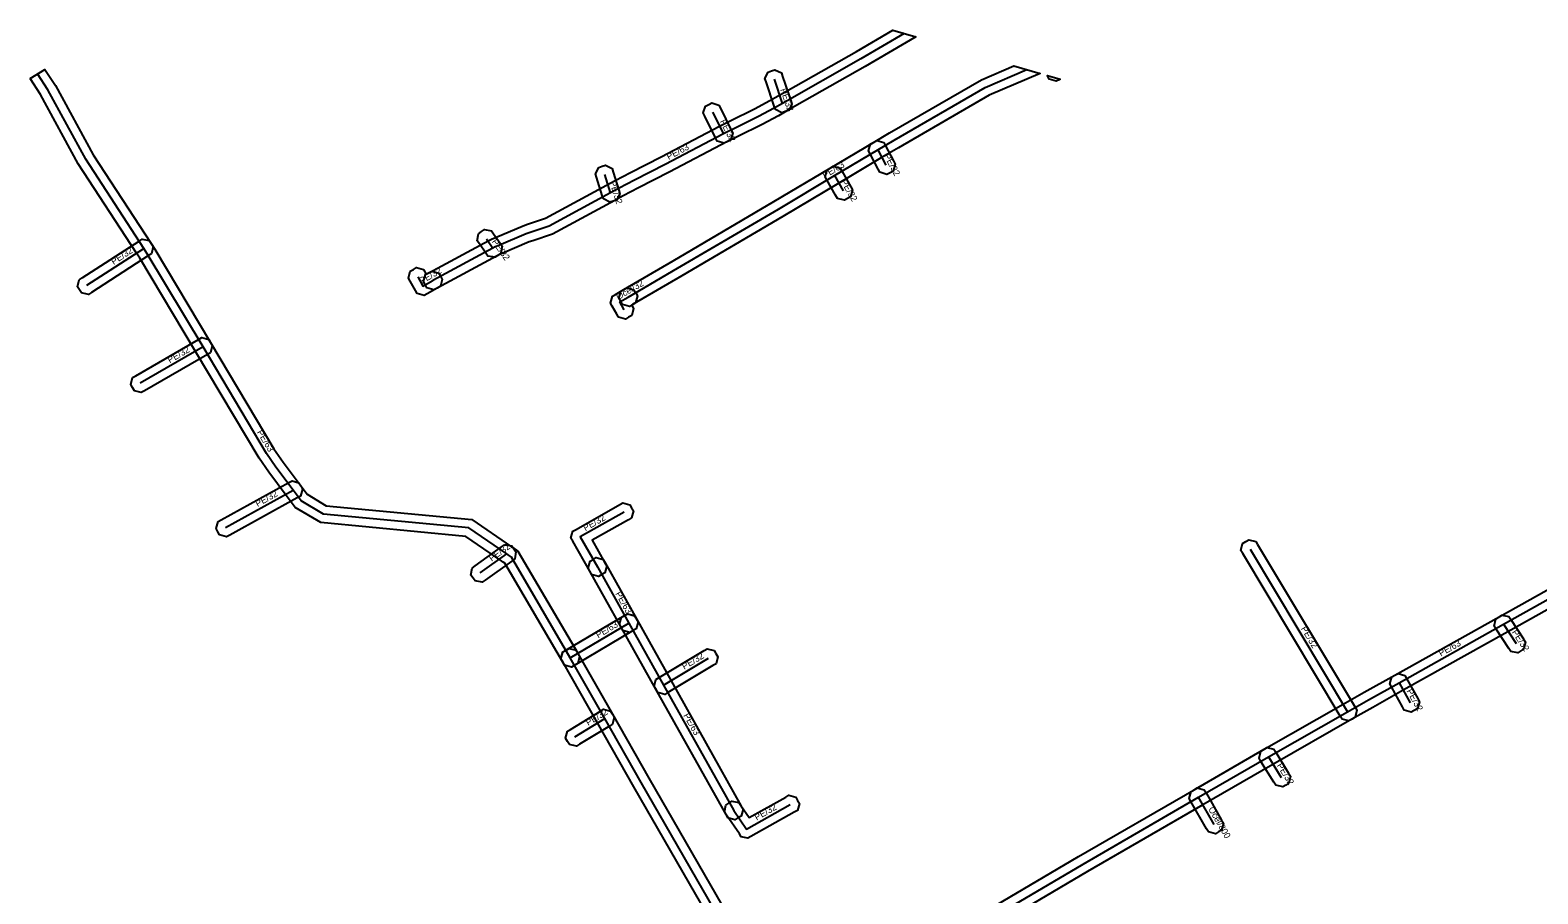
# Model space of a CAD drawing. Extents: x -574390 to -573768, y -1190959 to -1190603.
# Drawn here: x -574153.3 to -573979.8, y -1190702.4 to -1190603.1 of the extents above; entities that cross this region are included whole.
import ezdxf

# ---------------------------------------------------------------- set-up
doc = ezdxf.new("R2010")
doc.units = 0
for name, color, linetype in [('1', 7, 'Continuous'), ('24', 7, 'Continuous'), ('28', 7, 'Continuous'), ('30', 7, 'Continuous')]:
    doc.layers.add(name, color=color, linetype=linetype)

msp = doc.modelspace()

# ---------------------------------------------------------------- linework, layer by layer
at = {"layer": '1'}
for points in [[(-574058.179, -1190605.494), (-574054.01, -1190603.056), (-574051.371, -1190603.829), (-574057.181, -1190607.226), (-574066.205, -1190612.349), (-574067.176, -1190612.905), (-574069.024, -1190613.89), (-574071.846, -1190615.282), (-574072.739, -1190615.723), (-574073.038, -1190615.877), (-574079.739, -1190619.397), (-574083.264, -1190621.207), (-574085.032, -1190622.114), (-574086.012, -1190622.648), (-574093.161, -1190626.531), (-574095.428, -1190627.28), (-574095.85, -1190627.418), (-574098.964, -1190628.733), (-574099.33, -1190628.884), (-574099.545, -1190629), (-574106.455, -1190632.73), (-574106.82, -1190632.927), (-574107.613, -1190632.69), (-574107.81, -1190632.325), (-574108.007, -1190631.96), (-574107.77, -1190631.167), (-574107.405, -1190630.97), (-574100.495, -1190627.24), (-574100.19, -1190627.076), (-574099.736, -1190626.887), (-574096.55, -1190625.542), (-574096.052, -1190625.38), (-574093.959, -1190624.689), (-574086.968, -1190620.892), (-574085.968, -1190620.346), (-574084.178, -1190619.427), (-574080.661, -1190617.623), (-574073.962, -1190614.103), (-574073.641, -1190613.937), (-574072.73, -1190613.488), (-574069.936, -1190612.11), (-574068.144, -1190611.155), (-574067.195, -1190610.611)], [(-574153.281, -1190608.611), (-574151.577, -1190607.562), (-574150.371, -1190609.417), (-574146.021, -1190617.387), (-574139.361, -1190627.606), (-574138.95, -1190628.242), (-574132.532, -1190638.977), (-574125.228, -1190651.2), (-574124.177, -1190652.728), (-574122.218, -1190655.362), (-574121.419, -1190656.431), (-574119.202, -1190657.746), (-574102.458, -1190659.339), (-574097.88, -1190662.471), (-574097.728, -1190662.573), (-574097.149, -1190662.974), (-574090.257, -1190674.724), (-574090.048, -1190675.081), (-574090.257, -1190675.883), (-574090.614, -1190676.093), (-574090.971, -1190676.302), (-574091.773, -1190676.093), (-574091.983, -1190675.736), (-574098.651, -1190664.366), (-574098.852, -1190664.227), (-574099, -1190664.129), (-574103.162, -1190661.281), (-574119.838, -1190659.694), (-574122.781, -1190657.949), (-574123.822, -1190656.558), (-574125.803, -1190653.892), (-574126.912, -1190652.28), (-574134.248, -1190640.003), (-574140.65, -1190629.298), (-574141.039, -1190628.694), (-574147.739, -1190618.413), (-574152.089, -1190610.443)], [(-574043.82, -1190608.755), (-574040.073, -1190607.14), (-574037.065, -1190608.021), (-574042.92, -1190610.545), (-574053.365, -1190616.583), (-574055.22, -1190617.68), (-574060.209, -1190620.649), (-574066.672, -1190624.491), (-574078.284, -1190631.303), (-574083.955, -1190634.623), (-574084.312, -1190634.832), (-574085.114, -1190634.622), (-574085.323, -1190634.265), (-574085.532, -1190633.908), (-574085.322, -1190633.106), (-574084.965, -1190632.897), (-574079.296, -1190629.577), (-574067.688, -1190622.769), (-574061.231, -1190618.931), (-574056.24, -1190615.96), (-574054.375, -1190614.857)], [(-574067.515, -1190612.192), (-574067.648, -1190611.799), (-574068.588, -1190609.009), (-574068.72, -1190608.617), (-574068.352, -1190607.875), (-574067.959, -1190607.742), (-574067.567, -1190607.61), (-574066.825, -1190607.978), (-574066.692, -1190608.371), (-574065.752, -1190611.161), (-574065.62, -1190611.553), (-574065.988, -1190612.295), (-574066.381, -1190612.428), (-574066.773, -1190612.56)], [(-574036.192, -1190608.312), (-574036.213, -1190608.271), (-574034.746, -1190608.7), (-574034.848, -1190608.752), (-574035.217, -1190608.939), (-574036.005, -1190608.681)], [(-574074.041, -1190611.672), (-574073.856, -1190612.043), (-574072.606, -1190614.543), (-574072.42, -1190614.913), (-574072.682, -1190615.699), (-574073.053, -1190615.884), (-574073.423, -1190616.07), (-574074.209, -1190615.808), (-574074.394, -1190615.437), (-574075.644, -1190612.937), (-574075.83, -1190612.567), (-574075.568, -1190611.781), (-574075.197, -1190611.596), (-574074.827, -1190611.41)], [(-574055.041, -1190615.985), (-574054.847, -1190616.351), (-574053.917, -1190618.101), (-574053.723, -1190618.467), (-574053.965, -1190619.259), (-574054.331, -1190619.453), (-574054.697, -1190619.647), (-574055.489, -1190619.405), (-574055.683, -1190619.039), (-574056.613, -1190617.289), (-574056.807, -1190616.923), (-574056.565, -1190616.131), (-574056.199, -1190615.937), (-574055.833, -1190615.743)], [(-574087.32, -1190622.465), (-574087.444, -1190622.07), (-574088.104, -1190619.97), (-574088.228, -1190619.575), (-574087.845, -1190618.84), (-574087.45, -1190618.716), (-574087.055, -1190618.592), (-574086.32, -1190618.975), (-574086.196, -1190619.37), (-574085.536, -1190621.47), (-574085.412, -1190621.865), (-574085.795, -1190622.6), (-574086.19, -1190622.724), (-574086.585, -1190622.848)], [(-574060.056, -1190618.936), (-574059.851, -1190619.296), (-574058.851, -1190621.056), (-574058.646, -1190621.416), (-574058.866, -1190622.214), (-574059.226, -1190622.419), (-574059.586, -1190622.624), (-574060.384, -1190622.404), (-574060.589, -1190622.044), (-574061.589, -1190620.284), (-574061.794, -1190619.924), (-574061.574, -1190619.126), (-574061.214, -1190618.921), (-574060.854, -1190618.716)], [(-574100.189, -1190626.137), (-574099.951, -1190626.476), (-574099.201, -1190627.546), (-574098.963, -1190627.885), (-574099.107, -1190628.701), (-574099.446, -1190628.939), (-574099.785, -1190629.177), (-574100.601, -1190629.033), (-574100.839, -1190628.694), (-574101.589, -1190627.624), (-574101.827, -1190627.285), (-574101.683, -1190626.469), (-574101.344, -1190626.231), (-574101.005, -1190625.993)], [(-574147.651, -1190631.775), (-574147.303, -1190631.55), (-574140.743, -1190627.31), (-574140.395, -1190627.085), (-574139.585, -1190627.259), (-574139.36, -1190627.607), (-574139.135, -1190627.955), (-574139.309, -1190628.765), (-574139.657, -1190628.99), (-574146.217, -1190633.23), (-574146.565, -1190633.455), (-574147.375, -1190633.281), (-574147.6, -1190632.933), (-574147.825, -1190632.585)], [(-574108.014, -1190630.587), (-574107.81, -1190630.947), (-574107.702, -1190631.138), (-574107.422, -1190630.979), (-574107.061, -1190630.775), (-574106.263, -1190630.997), (-574106.059, -1190631.358), (-574105.855, -1190631.719), (-574106.077, -1190632.517), (-574106.438, -1190632.721), (-574107.588, -1190633.371), (-574107.948, -1190633.574), (-574108.746, -1190633.353), (-574108.95, -1190632.993), (-574109.55, -1190631.933), (-574109.754, -1190631.572), (-574109.533, -1190630.774), (-574109.173, -1190630.57), (-574108.812, -1190630.366)], [(-574085.576, -1190636.063), (-574085.78, -1190635.703), (-574086.29, -1190634.803), (-574086.494, -1190634.444), (-574086.275, -1190633.647), (-574085.917, -1190633.442), (-574084.957, -1190632.892), (-574084.597, -1190632.686), (-574083.798, -1190632.903), (-574083.592, -1190633.263), (-574083.386, -1190633.623), (-574083.603, -1190634.422), (-574083.963, -1190634.628), (-574084.059, -1190634.683), (-574084.04, -1190634.717), (-574083.836, -1190635.077), (-574084.057, -1190635.876), (-574084.417, -1190636.08), (-574084.777, -1190636.284)], [(-574132.531, -1190640.149), (-574132.89, -1190640.356), (-574140.13, -1190644.536), (-574140.489, -1190644.743), (-574141.289, -1190644.529), (-574141.496, -1190644.17), (-574141.703, -1190643.811), (-574141.489, -1190643.011), (-574141.13, -1190642.804), (-574133.89, -1190638.624), (-574133.531, -1190638.417), (-574132.731, -1190638.631), (-574132.524, -1190638.99), (-574132.317, -1190639.349)], [(-574131.646, -1190659.585), (-574131.284, -1190659.385), (-574123.504, -1190655.085), (-574123.142, -1190654.885), (-574122.345, -1190655.114), (-574122.145, -1190655.476), (-574121.945, -1190655.838), (-574122.174, -1190656.635), (-574122.536, -1190656.835), (-574130.316, -1190661.135), (-574130.678, -1190661.335), (-574131.475, -1190661.106), (-574131.675, -1190660.744), (-574131.875, -1190660.382)], [(-574084.077, -1190659.156), (-574084.438, -1190659.36), (-574088.605, -1190661.717), (-574087.131, -1190664.305), (-574086.926, -1190664.665), (-574087.145, -1190665.464), (-574087.505, -1190665.669), (-574087.865, -1190665.874), (-574088.664, -1190665.655), (-574088.869, -1190665.295), (-574090.839, -1190661.835), (-574091.044, -1190661.474), (-574090.934, -1190661.074), (-574090.824, -1190660.674), (-574090.462, -1190660.47), (-574085.422, -1190657.62), (-574085.062, -1190657.416), (-574084.264, -1190657.637), (-574084.06, -1190657.998), (-574083.856, -1190658.358)], [(-574102.419, -1190664.918), (-574102.082, -1190664.677), (-574099.022, -1190662.487), (-574098.685, -1190662.246), (-574097.868, -1190662.381), (-574097.627, -1190662.718), (-574097.386, -1190663.055), (-574097.521, -1190663.872), (-574097.858, -1190664.113), (-574100.918, -1190666.303), (-574101.255, -1190666.544), (-574102.072, -1190666.409), (-574102.313, -1190666.072), (-574102.554, -1190665.735)], [(-574012.235, -1190661.861), (-574012.022, -1190662.216), (-574000.812, -1190680.926), (-574000.599, -1190681.281), (-574000.801, -1190682.085), (-574001.156, -1190682.298), (-574001.511, -1190682.511), (-574002.315, -1190682.309), (-574002.528, -1190681.954), (-574013.738, -1190663.244), (-574013.951, -1190662.889), (-574013.749, -1190662.085), (-574013.394, -1190661.872), (-574013.039, -1190661.659)], [(-574087.33, -1190663.95), (-574087.127, -1190664.312), (-574083.517, -1190670.762), (-574083.315, -1190671.123), (-574083.54, -1190671.92), (-574083.902, -1190672.123), (-574084.263, -1190672.325), (-574085.06, -1190672.1), (-574085.263, -1190671.738), (-574088.873, -1190665.288), (-574089.075, -1190664.927), (-574088.85, -1190664.13), (-574088.488, -1190663.927), (-574088.127, -1190663.725)], [(-574091.986, -1190674.58), (-574091.629, -1190674.369), (-574084.899, -1190670.389), (-574084.542, -1190670.178), (-574083.74, -1190670.384), (-574083.529, -1190670.741), (-574083.318, -1190671.098), (-574083.524, -1190671.9), (-574083.881, -1190672.111), (-574090.611, -1190676.091), (-574090.968, -1190676.302), (-574091.77, -1190676.096), (-574091.981, -1190675.739), (-574092.192, -1190675.382)], [(-574083.72, -1190670.4), (-574083.517, -1190670.762), (-574079.528, -1190677.891), (-574071.448, -1190692.301), (-574071.245, -1190692.662), (-574071.47, -1190693.459), (-574071.831, -1190693.662), (-574072.192, -1190693.865), (-574072.989, -1190693.64), (-574073.192, -1190693.279), (-574081.272, -1190678.869), (-574085.263, -1190671.738), (-574085.465, -1190671.377), (-574085.24, -1190670.58), (-574084.878, -1190670.377), (-574084.517, -1190670.175)], [(-573983.12, -1190670.496), (-573982.893, -1190670.843), (-573981.443, -1190673.063), (-573981.216, -1190673.41), (-573981.386, -1190674.22), (-573981.733, -1190674.447), (-573982.08, -1190674.674), (-573982.89, -1190674.504), (-573983.117, -1190674.157), (-573984.567, -1190671.937), (-573984.794, -1190671.59), (-573984.624, -1190670.78), (-573984.277, -1190670.553), (-573983.93, -1190670.326)], [(-574081.269, -1190677.734), (-574080.914, -1190677.522), (-574075.734, -1190674.422), (-574075.378, -1190674.209), (-574074.574, -1190674.411), (-574074.362, -1190674.766), (-574074.149, -1190675.122), (-574074.351, -1190675.926), (-574074.706, -1190676.138), (-574079.886, -1190679.238), (-574080.242, -1190679.451), (-574081.046, -1190679.249), (-574081.258, -1190678.894), (-574081.471, -1190678.538)], [(-573995.073, -1190677.265), (-573994.874, -1190677.628), (-573993.604, -1190679.938), (-573993.404, -1190680.301), (-573993.635, -1190681.097), (-573993.998, -1190681.296), (-573994.361, -1190681.496), (-573995.157, -1190681.265), (-573995.356, -1190680.902), (-573996.626, -1190678.592), (-573996.826, -1190678.229), (-573996.595, -1190677.433), (-573996.232, -1190677.234), (-573995.869, -1190677.034)], [(-574091.463, -1190683.7), (-574091.109, -1190683.485), (-574087.649, -1190681.385), (-574087.295, -1190681.17), (-574086.49, -1190681.367), (-574086.275, -1190681.721), (-574086.06, -1190682.075), (-574086.257, -1190682.88), (-574086.611, -1190683.095), (-574090.071, -1190685.195), (-574090.425, -1190685.41), (-574091.23, -1190685.213), (-574091.445, -1190684.859), (-574091.66, -1190684.505)], [(-574010.156, -1190685.753), (-574009.939, -1190686.105), (-574008.459, -1190688.505), (-574008.242, -1190688.857), (-574008.433, -1190689.664), (-574008.785, -1190689.881), (-574009.137, -1190690.098), (-574009.944, -1190689.907), (-574010.161, -1190689.555), (-574011.641, -1190687.155), (-574011.858, -1190686.803), (-574011.667, -1190685.996), (-574011.315, -1190685.779), (-574010.963, -1190685.562)], [(-574017.689, -1190695.259), (-574017.896, -1190694.9), (-574019.696, -1190691.78), (-574019.903, -1190691.421), (-574019.689, -1190690.621), (-574019.33, -1190690.414), (-574018.971, -1190690.207), (-574018.171, -1190690.421), (-574017.964, -1190690.78), (-574016.164, -1190693.9), (-574015.957, -1190694.259), (-574016.171, -1190695.059), (-574016.53, -1190695.266), (-574016.889, -1190695.473)], [(-574071.731, -1190691.882), (-574071.496, -1190692.223), (-574070.534, -1190693.622), (-574066.319, -1190691.258), (-574065.958, -1190691.055), (-574065.161, -1190691.28), (-574064.958, -1190691.641), (-574064.755, -1190692.002), (-574064.98, -1190692.799), (-574065.341, -1190693.002), (-574070.351, -1190695.812), (-574070.689, -1190696.001), (-574071.444, -1190695.826), (-574071.664, -1190695.507), (-574073.144, -1190693.357), (-574073.379, -1190693.016), (-574073.228, -1190692.201), (-574072.887, -1190691.966), (-574072.546, -1190691.731)]]:
    msp.add_lwpolyline(points, close=True, dxfattribs=at)
for points in [[(-574044.527, -1190705.118), (-574032.624, -1190698.106), (-574019.331, -1190690.414), (-574011.288, -1190685.763), (-574002.164, -1190680.57), (-573999.761, -1190679.209), (-573996.238, -1190677.237), (-573984.218, -1190670.517), (-573976.478, -1190666.187)], [(-573975.502, -1190667.933), (-573983.242, -1190672.263), (-573995.262, -1190678.983), (-573998.779, -1190680.951), (-574001.176, -1190682.31), (-574010.292, -1190687.497), (-574018.329, -1190692.146), (-574031.616, -1190699.834), (-574043.513, -1190706.842)], [(-574074.657, -1190706.008), (-574083.818, -1190690.077), (-574087.999, -1190682.735), (-574091.989, -1190675.725), (-574092.194, -1190675.365), (-574091.975, -1190674.566), (-574091.615, -1190674.361), (-574091.255, -1190674.156), (-574090.456, -1190674.375), (-574090.251, -1190674.735), (-574086.261, -1190681.745), (-574082.082, -1190689.083), (-574072.923, -1190705.012)]]:
    msp.add_lwpolyline(points, dxfattribs=at)
at = {"layer": '24'}
for points in [[(-574052.690742, -1190603.442677), (-574057.68, -1190606.36), (-574066.7, -1190611.48), (-574067.66, -1190612.03), (-574069.48, -1190613), (-574072.288, -1190614.385), (-574073.19, -1190614.83), (-574073.5, -1190614.99), (-574080.2, -1190618.51), (-574083.721, -1190620.317), (-574085.5, -1190621.23), (-574086.49, -1190621.77), (-574093.56, -1190625.61), (-574095.74, -1190626.33), (-574096.2, -1190626.48), (-574099.35, -1190627.81), (-574099.76, -1190627.98), (-574100.02, -1190628.12), (-574106.93, -1190631.85)], [(-574091.12, -1190675.23), (-574097.9, -1190663.67), (-574098.29, -1190663.4), (-574098.44, -1190663.3), (-574102.81, -1190660.31), (-574119.52, -1190658.72), (-574122.1, -1190657.19), (-574123.02, -1190655.96), (-574124.99, -1190653.31), (-574126.07, -1190651.74), (-574133.39, -1190639.49), (-574139.8, -1190628.77), (-574140.2, -1190628.15), (-574146.88, -1190617.9), (-574151.23, -1190609.93), (-574152.428958, -1190608.086651)], [(-574084.46, -1190633.76), (-574078.79, -1190630.44), (-574067.18, -1190623.63), (-574060.72, -1190619.79), (-574055.73, -1190616.82), (-574053.87, -1190615.72), (-574043.37, -1190609.65), (-574038.568701, -1190607.580343)], [(-574074.75, -1190612.49), (-574073.5, -1190614.99)], [(-574055.73, -1190616.82), (-574054.8, -1190618.57)], [(-574060.72, -1190619.79), (-574059.72, -1190621.55)], [(-574100.77, -1190627.05), (-574100.02, -1190628.12)], [(-574146.76, -1190632.39), (-574140.2, -1190628.15)], [(-574108.68, -1190631.44), (-574108.08, -1190632.5), (-574106.93, -1190631.85)], [(-574084.91, -1190635.21), (-574085.42, -1190634.31), (-574084.46, -1190633.76)], [(-574052.27, -1190712.36), (-574049.75, -1190709.58), (-574045.72, -1190706.98), (-574044.02, -1190705.98), (-574032.12, -1190698.97), (-574018.83, -1190691.28), (-574010.79, -1190686.63), (-574001.67, -1190681.44), (-573999.27, -1190680.08), (-573995.75, -1190678.11), (-573983.73, -1190671.39), (-573975.99, -1190667.06), (-573969.47, -1190663.41), (-573965.82, -1190661.37), (-573959.87, -1190658), (-573951.88, -1190653.46), (-573950.37, -1190652.6), (-573943.33, -1190648.61), (-573936.84, -1190644.93), (-573934.69, -1190643.69), (-573928.142665, -1190639.934461)], [(-574130.8, -1190660.26), (-574123.02, -1190655.96)], [(-574084.93, -1190658.49), (-574089.97, -1190661.34), (-574088, -1190664.8)], [(-574101.5, -1190665.49), (-574098.44, -1190663.3)], [(-574088, -1190664.8), (-574084.39, -1190671.25)], [(-574091.12, -1190675.23), (-574084.39, -1190671.25)], [(-574084.39, -1190671.25), (-574080.4, -1190678.38), (-574072.32, -1190692.79)], [(-573983.73, -1190671.39), (-573982.28, -1190673.61)], [(-574033.08, -1190777.7), (-574034.01, -1190776.47), (-574038.3, -1190768.93), (-574044.12, -1190758.71), (-574045.11, -1190756.97), (-574047.59, -1190752.62), (-574048.73, -1190750.62), (-574055.8, -1190738.19), (-574056.1, -1190737.67), (-574060.21, -1190730.26), (-574060.63, -1190729.5), (-574069.65, -1190713.22), (-574072.78, -1190707.27), (-574073.79, -1190705.51), (-574082.95, -1190689.58), (-574087.13, -1190682.24), (-574091.12, -1190675.23)], [(-574080.4, -1190678.38), (-574075.22, -1190675.28)], [(-573995.75, -1190678.11), (-573994.48, -1190680.42)], [(-574090.59, -1190684.34), (-574087.13, -1190682.24)], [(-574010.79, -1190686.63), (-574009.31, -1190689.03)], [(-574072.32, -1190692.79), (-574070.84, -1190694.94), (-574065.83, -1190692.13)]]:
    msp.add_lwpolyline(points, dxfattribs=at)
at = {"layer": '28'}
for points in [[(-574066.7, -1190611.48), (-574067.64, -1190608.69)], [(-574086.49, -1190621.77), (-574087.15, -1190619.67)], [(-574133.39, -1190639.49), (-574140.63, -1190643.67)], [(-574012.88, -1190662.73), (-574001.67, -1190681.44)], [(-574017.03, -1190694.4), (-574018.83, -1190691.28)]]:
    msp.add_lwpolyline(points, dxfattribs=at)

# ---------------------------------------------------------------- texts
at = {"layer": '30'}
for s, rotation, p in [('PE/32', 288.61957476, (-574066.97, -1190609.885)), ('PE/32', 296.56505118, (-574073.925, -1190613.54)), ('PE/63', 27.71622988, (-574079.80103, -1190617.995317)), ('PE/32', 297.98745319, (-574055.065, -1190617.495)), ('PE/63', 30.72840322, (-574061.831579, -1190620.131867)), ('PE/32', 287.44718842, (-574086.62, -1190620.52)), ('PE/32', 299.60445075, (-574060.02, -1190620.47)), ('PE/32', 305.02794231, (-574100.195, -1190627.385)), ('PE/32', 32.87626175, (-574143.68, -1190630.07)), ('PE/32', 29.475889, (-574108.235186, -1190632.274671)), ('Ocel/32', 29.80911421, (-574085.588792, -1190634.09212)), ('PE/32', 29.99990534, (-574137.21, -1190641.38)), ('PE/63', 300.86047138, (-574127.211887, -1190649.294355)), ('PE/32', 28.92939499, (-574127.11, -1190657.91)), ('PE/32', 29.48712567, (-574089.382889, -1190660.694908)), ('PE/32', 35.59077859, (-574100.17, -1190664.195)), ('PE/63', 299.23529978, (-574085.97058, -1190667.868631)), ('PE/63', 30.59930047, (-574087.911963, -1190673.014548)), ('PE/32', 300.92771579, (-574007.075, -1190671.885)), ('PE/32', 303.15068805, (-573982.805, -1190672.3)), ('PE/32', 30.89864772, (-574078.01, -1190676.63)), ('PE/63', 29.20816838, (-573990.938962, -1190675.108488)), ('PE/32', 298.80127143, (-573994.915, -1190679.065)), ('PE/32', 31.25508849, (-574089.06, -1190683.09)), ('PE/63', 299.28029623, (-574078.133569, -1190681.865305)), ('PE/32', 301.6607511, (-574009.85, -1190687.63)), ('PE/32', 29.28711867, (-574069.673261, -1190693.973426)), ('Ocel/800', 299.98163937, (-574017.73, -1190692.64))]:
    msp.add_text(s, height=0.75, rotation=rotation, dxfattribs=at).set_placement(p)

doc.saveas('drawing.dxf')
